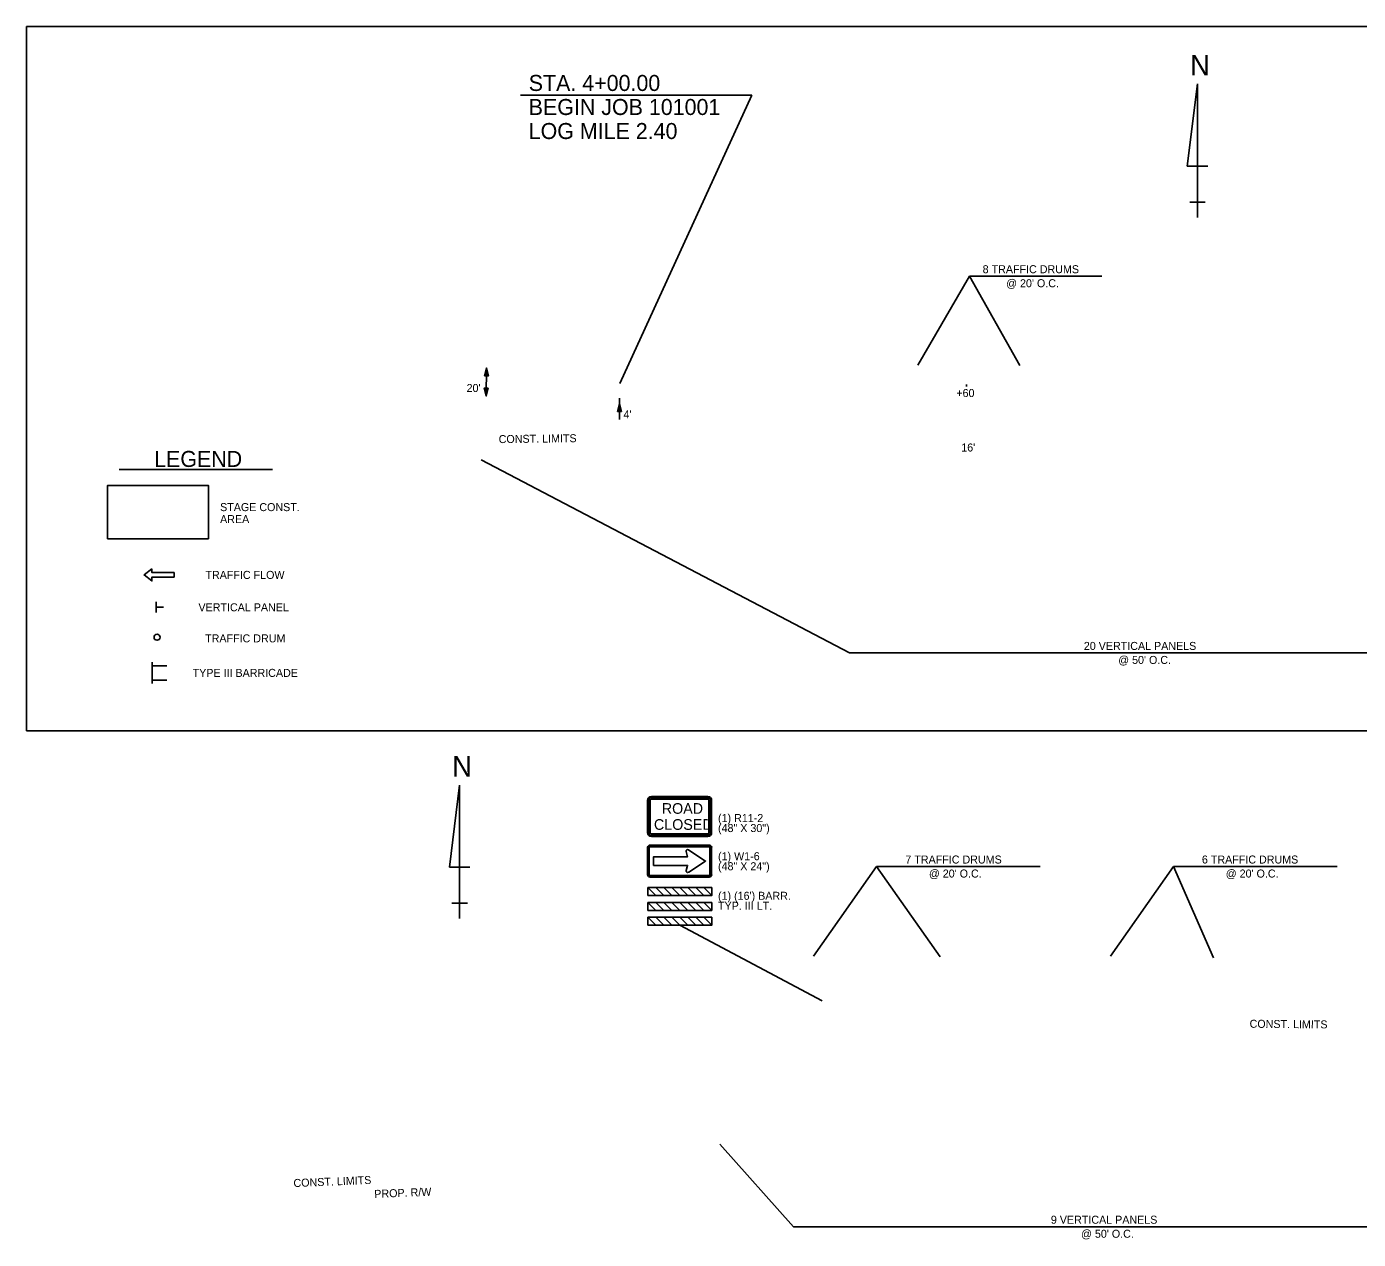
# Model space of a CAD drawing. Extents: x 1939303 to 1940899, y 534003 to 535040.
# Drawn here: x 1939303 to 1940301, y 534131 to 535040 of the extents above; entities that cross this region are included whole.
import ezdxf

# ---------------------------------------------------------------- set-up
doc = ezdxf.new("R2010")
doc.units = 0
for name, color, linetype in [('Default', 7, 'Continuous'), ('Level 1', 7, 'Continuous'), ('Level 2', 7, 'Continuous'), ('Level 3', 7, 'Continuous'), ('Level 4', 7, 'Continuous'), ('R_Annotation', 7, 'Continuous'), ('R_Border', 7, 'Continuous'), ('S_BASELINE', 7, 'Continuous')]:
    doc.layers.add(name, color=color, linetype=linetype)

msp = doc.modelspace()

# ---------------------------------------------------------------- linework, layer by layer
at = {"layer": 'Default'}
for p, q in [((1940180.97, 534996.62), (1940173.28, 534935.08)), ((1940180.97, 534896.62), (1940180.97, 534996.62)), ((1940180.97, 534996.62), (1940180.97, 534919.69)), ((1940173.28, 534935.08), (1940188.67, 534935.08)), ((1940180.97, 534896.62), (1940180.97, 534919.69)), ((1940180.97, 534908.15), (1940175.2, 534908.15)), ((1940175.2, 534908.15), (1940186.74, 534908.15)), ((1940180.97, 534896.62), (1940180.97, 534908.15)), ((1939627.89, 534471.27), (1939620.2, 534409.74)), ((1939627.89, 534371.27), (1939627.89, 534471.27)), ((1939627.89, 534471.27), (1939627.89, 534394.35)), ((1939620.2, 534409.74), (1939635.58, 534409.74)), ((1939627.89, 534371.27), (1939627.89, 534394.35)), ((1939627.89, 534382.81), (1939622.12, 534382.81)), ((1939622.12, 534382.81), (1939633.66, 534382.81)), ((1939627.89, 534371.27), (1939627.89, 534382.81))]:
    msp.add_line(p, q, dxfattribs=at)
at = {"layer": 'Level 1'}
for p, q in [((1939400.44, 534600.66), (1939400.44, 534608.66)), ((1939400.56, 534604.64), (1939406.02, 534604.64)), ((1939397.54, 534563.33), (1939397.54, 534547.33)), ((1939408.46, 534560.69), (1939397.54, 534560.69)), ((1939408.46, 534549.83), (1939397.54, 534549.83))]:
    msp.add_line(p, q, dxfattribs=at)
msp.add_lwpolyline([(1939397.24, 534633.27), (1939391.4, 534628.77), (1939397.24, 534624.27), (1939397.24, 534627.08), (1939413.79, 534627.08), (1939413.79, 534630.46), (1939397.24, 534630.46)], close=True, dxfattribs=at)
at = {"layer": 'Level 2'}
msp.add_circle((1939401.08, 534582.06), 2.25, dxfattribs=at)
at = {"layer": 'Level 3'}
for p, q in [((1939816.95, 534394.54), (1939768.92, 534394.54)), ((1939768.92, 534388.51), (1939768.92, 534394.54)), ((1939816.95, 534388.51), (1939816.95, 534394.54)), ((1939768.96, 534388.53), (1939768.92, 534388.57)), ((1939816.95, 534388.51), (1939768.92, 534388.51)), ((1939816.95, 534383.37), (1939768.92, 534383.37)), ((1939768.92, 534377.35), (1939768.92, 534383.37)), ((1939768.92, 534377.35), (1939768.92, 534383.37)), ((1939816.95, 534377.35), (1939816.95, 534383.37)), ((1939816.95, 534377.35), (1939768.92, 534377.35)), ((1939816.95, 534372.22), (1939768.92, 534372.22)), ((1939768.92, 534366.21), (1939768.92, 534372.22)), ((1939816.95, 534366.21), (1939816.95, 534372.22)), ((1939816.95, 534366.21), (1939768.92, 534366.21))]:
    msp.add_line(p, q, dxfattribs=at)
for points in [[(1939768.92, 534394.54), (1939774.83, 534394.53), (1939780.82, 534388.53), (1939774.94, 534388.53)], [(1939780.92, 534394.54), (1939786.83, 534394.53), (1939792.82, 534388.53), (1939786.94, 534388.53)], [(1939792.92, 534394.54), (1939798.83, 534394.53), (1939804.82, 534388.53), (1939798.94, 534388.53)], [(1939804.92, 534394.54), (1939810.83, 534394.53), (1939816.82, 534388.53), (1939810.94, 534388.53)], [(1939768.92, 534383.37), (1939774.83, 534383.35), (1939780.82, 534377.35), (1939774.94, 534377.35)], [(1939780.92, 534383.37), (1939786.83, 534383.35), (1939792.82, 534377.35), (1939786.94, 534377.35)], [(1939792.92, 534383.37), (1939798.83, 534383.35), (1939804.82, 534377.35), (1939798.94, 534377.35)], [(1939804.92, 534383.37), (1939810.83, 534383.35), (1939816.82, 534377.35), (1939810.94, 534377.35)], [(1939768.92, 534372.22), (1939774.83, 534372.21), (1939780.82, 534366.21), (1939774.94, 534366.21)], [(1939780.92, 534372.22), (1939786.83, 534372.21), (1939792.82, 534366.21), (1939786.94, 534366.21)], [(1939792.92, 534372.22), (1939798.83, 534372.21), (1939804.82, 534366.21), (1939798.94, 534366.21)], [(1939804.92, 534372.22), (1939810.83, 534372.21), (1939816.82, 534366.21), (1939810.94, 534366.21)]]:
    msp.add_lwpolyline(points, close=True, dxfattribs=at)
at = {"layer": 'Level 4'}
for p, q in [((1939768.76, 534459.94), (1939768.76, 534435.54)), ((1939769.56, 534459.94), (1939769.56, 534435.54)), ((1939770.76, 534459.94), (1939770.76, 534435.54)), ((1939813.96, 534462.74), (1939771.56, 534462.74)), ((1939813.96, 534461.94), (1939771.56, 534461.94)), ((1939813.96, 534460.74), (1939771.56, 534460.74)), ((1939814.76, 534435.54), (1939814.76, 534459.94)), ((1939815.96, 534435.54), (1939815.96, 534459.94)), ((1939816.76, 534435.54), (1939816.76, 534459.94)), ((1939771.56, 534434.74), (1939813.96, 534434.74)), ((1939771.56, 534433.54), (1939813.96, 534433.54)), ((1939771.56, 534432.74), (1939813.96, 534432.74)), ((1939768.77, 534424.46), (1939768.77, 534404.21)), ((1939769.27, 534424.46), (1939769.27, 534404.21)), ((1939770.02, 534424.46), (1939770.02, 534404.21)), ((1939814.9, 534426.34), (1939770.65, 534426.34)), ((1939814.9, 534425.84), (1939770.65, 534425.84)), ((1939814.9, 534425.09), (1939770.65, 534425.09)), ((1939815.52, 534404.21), (1939815.52, 534424.46)), ((1939816.27, 534404.21), (1939816.27, 534424.46)), ((1939816.77, 534404.21), (1939816.77, 534424.46)), ((1939770.65, 534403.59), (1939814.9, 534403.59)), ((1939770.65, 534402.84), (1939814.9, 534402.84)), ((1939770.65, 534402.34), (1939814.9, 534402.34))]:
    msp.add_line(p, q, dxfattribs=at)
for points in [[(1939797.64, 534421.43), (1939798.78, 534417.59), (1939773.27, 534417.59), (1939773.27, 534411.09), (1939798.78, 534411.09), (1939797.61, 534407.25)], [(1939799.61, 534406.04), (1939812.27, 534414.34), (1939799.6, 534422.61)]]:
    msp.add_lwpolyline(points, dxfattribs=at)
for centre, radius, start, end in [((1939771.56, 534459.94), 2.8, 90, 180), ((1939771.56, 534459.94), 2, 90, 180), ((1939771.56, 534459.94), 0.8, 90, 180), ((1939813.96, 534459.94), 2.8, 0, 90), ((1939813.96, 534459.94), 2, 0, 90), ((1939813.96, 534459.94), 0.8, 0, 90), ((1939771.56, 534435.54), 2.8, 180, 270), ((1939771.56, 534435.54), 2, 180, 270), ((1939771.56, 534435.54), 0.8, 180, 270), ((1939813.96, 534435.54), 2.8, 270, 0), ((1939813.96, 534435.54), 2, 270, 0), ((1939813.96, 534435.54), 0.8, 270, 0), ((1939770.65, 534424.46), 1.87, 90, 180), ((1939770.65, 534424.46), 1.37, 90, 180), ((1939770.65, 534424.46), 0.625, 90, 180), ((1939798.77, 534421.75), 1.18, 56.59943, 195.96908), ((1939826.94, 534464.47), 50, 236.59943, 236.85697), ((1939814.9, 534424.46), 1.88, 0, 90), ((1939814.9, 534424.46), 1.38, 0, 90), ((1939814.9, 534424.46), 0.625, 0, 90), ((1939770.65, 534404.21), 1.88, 180, 270), ((1939770.65, 534404.21), 1.38, 180, 270), ((1939770.65, 534404.21), 0.625, 180, 270), ((1939798.77, 534406.92), 1.2, 164.03093, 303.47548), ((1939827.01, 534364.22), 50, 123.2286, 123.47548), ((1939814.9, 534404.21), 1.88, 270, 0), ((1939814.9, 534404.21), 1.38, 270, 0), ((1939814.9, 534404.21), 0.625, 270, 0)]:
    msp.add_arc(centre, radius, start, end, dxfattribs=at)
at = {"layer": 'R_Annotation'}
msp.add_line((1939303.34, 534511.95), (1940898.7, 534511.95), dxfattribs=at)
at = {"layer": 'R_Border'}
msp.add_lwpolyline([(1940898.7, 534838.67), (1940898.7, 534511.95), (1939303.34, 534511.95), (1939303.34, 535039.57), (1940487.4, 535039.57), (1940487.4, 534990.17), (1940664.99, 534990.17), (1940664.99, 534972.32), (1940683.2, 534972.32), (1940683.2, 534975.57), (1940760.87, 534975.57)], dxfattribs=at)
at = {"layer": 'S_BASELINE'}
for p, q in [((1939673.54, 534988.15), (1939846.76, 534988.15)), ((1939846.76, 534988.15), (1939747.85, 534772.29)), ((1940010.08, 534852.49), (1940109.16, 534852.49)), ((1939647.95, 534783.85), (1939647.77, 534762.77)), ((1940007.86, 534770.04), (1940007.87, 534771.54)), ((1939747.76, 534761.29), (1939747.72, 534757.29)), ((1939747.72, 534757.29), (1939747.62, 534745.3)), ((1939372.77, 534707.78), (1939487.53, 534707.78)), ((1939940.41, 534410.24), (1940063, 534410.24)), ((1940162.93, 534410.24), (1940285.52, 534410.24)), ((1939792.94, 534366.21), (1939899.49, 534309.65))]:
    msp.add_line(p, q, dxfattribs=at)
for points in [[(1939971.4, 534785.97), (1940010.08, 534852.49), (1940047.74, 534785.72)], [(1939643.97, 534715.02), (1939919.96, 534570.29), (1940596.07, 534570.29), (1940665.52, 534657.33)], [(1939893.14, 534342.96), (1939940.41, 534410.24), (1939987.93, 534342.46)], [(1940115.66, 534342.96), (1940162.93, 534410.24), (1940192.93, 534341.9)], [(1939822.92, 534202.3), (1939878.21, 534140.34), (1940353.29, 534140.34), (1940426.03, 534273.79)]]:
    msp.add_lwpolyline(points, dxfattribs=at)
for points in [[(1939646.4, 534777.86), (1939647.95, 534783.85), (1939649.4, 534777.83)], [(1939649.32, 534768.76), (1939647.77, 534762.77), (1939646.32, 534768.78)], [(1939746.17, 534751.31), (1939747.72, 534757.29), (1939749.17, 534751.28)], [(1939363.98, 534655.79), (1939439.53, 534655.79), (1939439.53, 534695.79), (1939363.98, 534695.79)]]:
    msp.add_lwpolyline(points, close=True, dxfattribs=at)

# ---------------------------------------------------------------- texts
at = {"layer": 'Default'}
for p in [(1940175.34, 535003.03), (1939622.26, 534477.68)]:
    msp.add_text('N', height=15.38, dxfattribs=at).set_placement(p)
at = {"layer": 'Level 4'}
for s, p in [('ROAD', (1939779.4, 534449.74)), ('CLOSED', (1939773.52, 534437.74))]:
    msp.add_text(s, height=8, dxfattribs=at).set_placement(p)
at = {"layer": 'S_BASELINE'}
for s, height, rotation, p in [('STA. 4+00.00', 12, 360, (1939679.65, 534991.36)), ('BEGIN JOB 101001', 12, 360, (1939679.65, 534973.36)), ('LOG MILE 2.40', 12, 360, (1939679.65, 534955.36)), ('CONST. LIMITS', 6, 0.68288, (1939657.18, 534727.49)), ('LEGEND', 12, 360, (1939398.9, 534709.65)), ('STAGE CONST.', 6, 360, (1939448.34, 534676.55)), ('AREA', 6, 360, (1939448.34, 534667.55)), ('(1) W1-6 ', 6, 359.98384, (1939821.54, 534414.98)), ('(48" X 24")', 6, 359.98384, (1939821.54, 534407.47)), ('CONST. LIMITS', 6, 359.49192, (1940219.92, 534289.45)), ('CONST. LIMITS', 6, 2.35984, (1939503.45, 534170.03)), ('PROP. R/W', 6, 2.25428, (1939564.02, 534161.9))]:
    msp.add_text(s, height=height, rotation=rotation, dxfattribs=at).set_placement(p)
for s, p in [('8 TRAFFIC DRUMS', (1940019.89, 534854.8)), ("@ 20' O.C.", (1940037.51, 534844.3)), ("20'", (1939633.08, 534765.82)), ('+60', (1940000.15, 534762.04)), ("4'", (1939750.67, 534746.07)), ("16'", (1940003.85, 534721.22)), ('TRAFFIC FLOW', (1939437.35, 534625.75)), ('VERTICAL PANEL', (1939432.11, 534601.47)), ('TRAFFIC DRUM', (1939437.11, 534578.2)), ('20 VERTICAL PANELS', (1940095.71, 534572.54)), ("@ 50' O.C.", (1940121.5, 534562.04)), ('TYPE III BARRICADE', (1939427.76, 534552.33)), ('(1) R11-2', (1939821.54, 534443.58)), ('(48" X 30")', (1939821.54, 534436.07)), ('7 TRAFFIC DRUMS', (1939961.97, 534412.49)), ('6 TRAFFIC DRUMS', (1940184.21, 534412.49)), ("@ 20' O.C.", (1939979.6, 534401.99)), ("@ 20' O.C.", (1940202.11, 534401.99)), ("(1) (16') BARR.", (1939821.54, 534385.31)), ('TYP. III LT.', (1939821.54, 534377.8)), ('9 VERTICAL PANELS', (1940071.01, 534142.59)), ("@ 50' O.C.", (1940093.64, 534132.09))]:
    msp.add_text(s, height=6, dxfattribs=at).set_placement(p)

doc.saveas('drawing.dxf')
